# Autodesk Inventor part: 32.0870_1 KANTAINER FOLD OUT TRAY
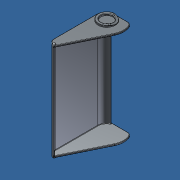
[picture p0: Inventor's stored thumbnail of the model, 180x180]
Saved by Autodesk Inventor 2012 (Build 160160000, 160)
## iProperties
Created: 2013-07
Part Number: 32.0870_1 KANTAINER FOLD OUT TRAY
Material: Default
Document SubType Name: Modeling
Designer: Admin
Density: 1 g/cm^3
Author: Admin
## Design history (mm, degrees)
node "001049371"
node "Volumenkörper1"
node "Base1"
